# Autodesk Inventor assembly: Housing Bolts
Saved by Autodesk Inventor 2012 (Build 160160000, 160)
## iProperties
Created: 2011-01
Part Number: Housing Bolts
Document SubType Name: Assembly
Designer: Beta-8540w
ClientObjectVersion: 1
Author: Beta-8540w
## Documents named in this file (4)
- C:\Users\VMuser\Desktop\Inventor 2012 Essentials\Assemblies\Chapter 8\Design Accelerators\Bolted Connection c8-02.iam
- C:\Users\VMuser\Desktop\Inventor 2012 Essentials\Content Center Files\en-US\ISO 8738\ISO 8738 - 4.ipt
- C:\Users\VMuser\Desktop\Inventor 2012 Essentials\Content Center Files\en-US\DIN 128\DIN 128 - A4.ipt
- C:\Users\VMuser\Desktop\Inventor 2012 Essentials\Content Center Files\en-US\ISO 4017\ISO 4017 - M4 x 8ISO.ipt
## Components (3 placed, 3 different names)
1. DIN EN 28738 4:1
2. DIN 128 A4:1
3. ISO 4017 M4 x 8:1
